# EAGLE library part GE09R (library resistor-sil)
SIL RESISTOR
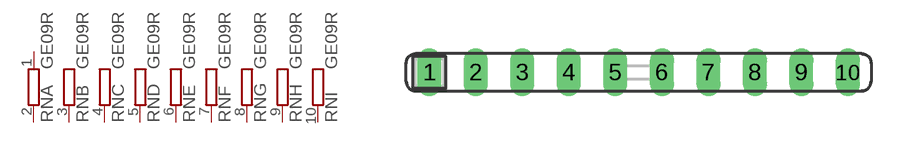
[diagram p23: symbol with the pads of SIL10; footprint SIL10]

Designator prefix RN; gates A=R-NV B=R-NV1 C=R-NV1 D=R-NV1 E=R-NV1 F=R-NV1 G=R-NV1 H=R-NV1 I=R-NV1

## GE09R (OC_FARNELL: unknown; OC_NEWARK: unknown)  [SIL10]
1  A:1  pas
2  A:2  pas
3  B:2  pas
4  C:2  pas
5  D:2  pas
6  E:2  pas
7  F:2  pas
8  G:2  pas
9  H:2  pas
10  I:2  pas

## Footprint SIL10 (pad centres in mm)
Single In Line
drill 0.813 long: 1 -11.43,0; 2 -8.89,0; 3 -6.35,0; 4 -3.81,0; 5 -1.27,0; 6 1.27,0; 7 3.81,0; 8 6.35,0; 9 8.89,0; 10 11.43,0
